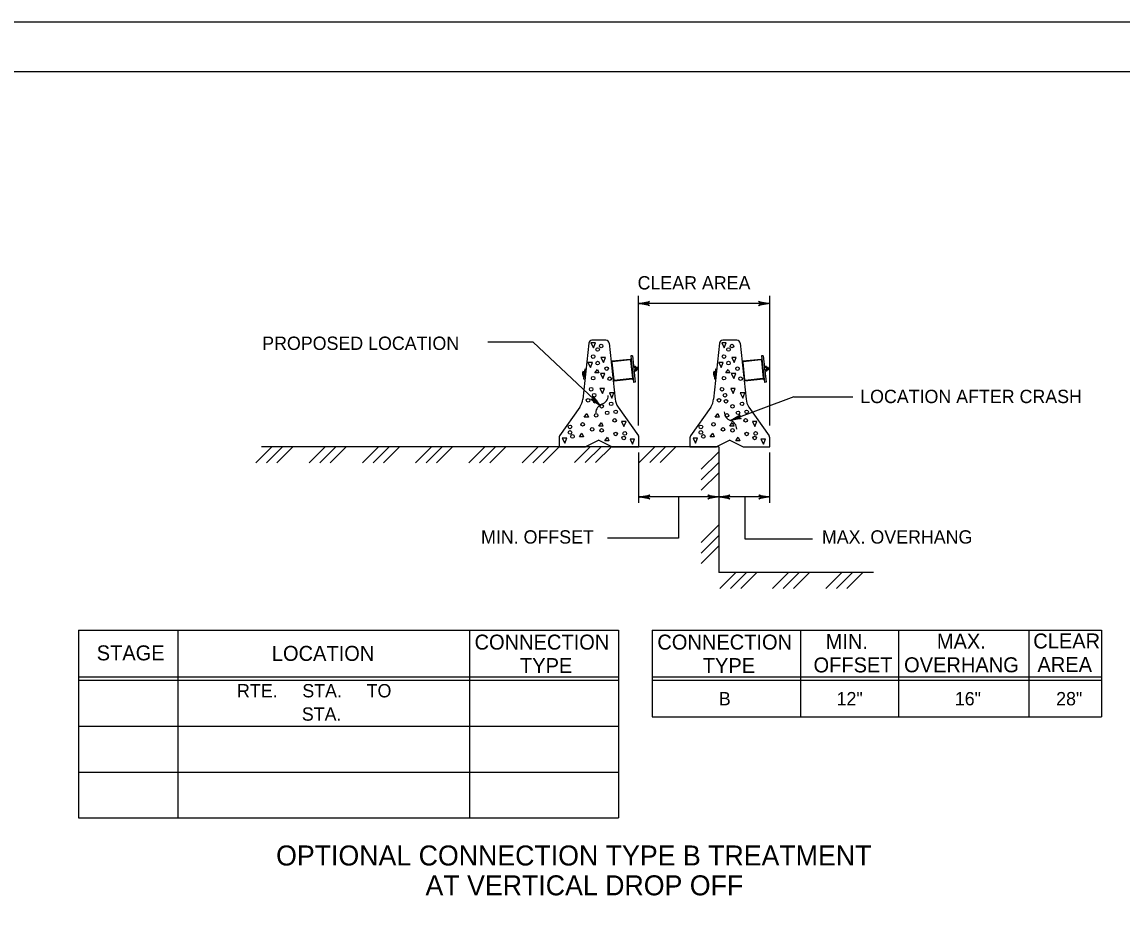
# Model space of a CAD drawing. Extents: x 499909 to 500993, y 502505 to 503165.
# Drawn here: x 500297.3 to 500627.6, y 502894.5 to 503165 of the extents above; entities that cross this region are included whole.
import ezdxf

# ---------------------------------------------------------------- set-up
doc = ezdxf.new("R2010")
doc.units = 0
for name, color, linetype in [('1', 7, 'Continuous'), ('24', 7, 'Continuous'), ('3', 7, 'Continuous'), ('41', 7, 'Continuous'), ('5', 7, 'Continuous')]:
    doc.layers.add(name, color=color, linetype=linetype)

msp = doc.modelspace()

# ---------------------------------------------------------------- linework, layer by layer
at = {"layer": '1'}
for p, q in [((500993, 503165), (499944.83, 503165)), ((500990, 503150), (500000, 503150)), ((500367.51, 503032.66), (500372.22, 503037.37)), ((500506.51, 503037.49), (500369.24, 503037.49)), ((500370.71, 503032.66), (500375.43, 503037.37)), ((500373.82, 503032.66), (500378.53, 503037.37)), ((500383.5, 503032.66), (500388.21, 503037.37)), ((500386.7, 503032.66), (500391.41, 503037.37)), ((500389.8, 503032.66), (500394.52, 503037.37)), ((500399.48, 503032.66), (500404.2, 503037.37)), ((500402.69, 503032.66), (500407.4, 503037.37)), ((500405.79, 503032.66), (500410.5, 503037.37)), ((500415.47, 503032.66), (500420.18, 503037.37)), ((500418.68, 503032.66), (500423.39, 503037.37)), ((500421.78, 503032.66), (500426.49, 503037.37)), ((500431.46, 503032.66), (500436.17, 503037.37)), ((500434.66, 503032.66), (500439.38, 503037.37)), ((500437.77, 503032.66), (500442.48, 503037.37)), ((500447.45, 503032.66), (500452.16, 503037.37)), ((500450.65, 503032.66), (500455.36, 503037.37)), ((500453.76, 503032.66), (500458.47, 503037.37)), ((500463.22, 503032.78), (500467.93, 503037.49)), ((500466.42, 503032.78), (500471.14, 503037.49)), ((500469.53, 503032.78), (500474.24, 503037.49)), ((500482.61, 503032.78), (500487.32, 503037.49)), ((500485.81, 503032.78), (500490.52, 503037.49)), ((500488.91, 503032.78), (500493.63, 503037.49)), ((500501.24, 503030.74), (500506.51, 503036.01)), ((500506.51, 503037.49), (500506.51, 502999.74)), ((500501.24, 503027.53), (500506.51, 503032.8)), ((500501.24, 503024.43), (500506.51, 503029.7)), ((500501.24, 503008.75), (500506.51, 503014.02)), ((500501.24, 503005.55), (500506.51, 503010.82)), ((500501.24, 503002.44), (500506.51, 503007.72)), ((500552.96, 502999.74), (500506.51, 502999.74)), ((500506.83, 502994.97), (500511.55, 502999.69)), ((500510.04, 502994.97), (500514.75, 502999.69)), ((500513.14, 502994.97), (500517.85, 502999.69)), ((500522.62, 502994.97), (500527.33, 502999.69)), ((500525.82, 502994.97), (500530.53, 502999.69)), ((500528.92, 502994.97), (500533.64, 502999.69)), ((500538.68, 502994.97), (500543.39, 502999.69)), ((500541.88, 502994.97), (500546.59, 502999.69)), ((500544.99, 502994.97), (500549.7, 502999.69)), ((500314.25, 502982.41), (500314.25, 502926.08)), ((500314.25, 502982.41), (500344.11, 502982.41)), ((500344.11, 502982.41), (500344.11, 502926.08)), ((500344.11, 502982.41), (500431.62, 502982.41)), ((500431.62, 502982.41), (500431.62, 502926.08)), ((500431.62, 502982.41), (500476.34, 502982.41)), ((500476.34, 502982.41), (500476.34, 502926.08)), ((500486.54, 502982.41), (500621.37, 502982.41)), ((500486.54, 502982.41), (500486.54, 502956.43)), ((500531.04, 502982.41), (500531.04, 502956.43)), ((500560.49, 502982.41), (500560.49, 502956.43)), ((500599.63, 502982.41), (500599.63, 502956.43)), ((500621.37, 502982.41), (500621.37, 502956.43)), ((500314.25, 502968.42), (500476.34, 502968.42)), ((500314.25, 502967.42), (500476.34, 502967.42)), ((500486.54, 502968.42), (500621.37, 502968.42)), ((500486.54, 502967.42), (500621.37, 502967.42)), ((500486.54, 502956.43), (500621.37, 502956.43)), ((500314.25, 502953.64), (500476.34, 502953.64)), ((500314.25, 502939.86), (500476.34, 502939.86)), ((500314.25, 502926.08), (500476.34, 502926.08))]:
    msp.add_line(p, q, dxfattribs=at)
at = {"layer": '24'}
for points in [[(500482.35, 503080.5), (500485.67, 503081.09), (500484.88, 503080.5), (500485.66, 503079.92), (500482.35, 503080.5), (500482.57, 503080.49), (500485.58, 503081.04), (500484.82, 503080.49), (500485.52, 503079.97), (500482.69, 503080.48), (500482.8, 503080.5), (500485.38, 503080.96), (500484.8, 503080.49), (500485.39, 503080.04), (500482.85, 503080.5), (500482.96, 503080.48), (500485.21, 503080.89), (500484.78, 503080.5), (500485.22, 503080.09), (500483.28, 503080.48), (500483.47, 503080.48), (500485.05, 503080.8), (500484.74, 503080.51), (500485.07, 503080.18), (500483.5, 503080.5), (500483.68, 503080.51), (500484.87, 503080.71), (500484.64, 503080.48), (500484.89, 503080.25), (500483.84, 503080.5), (500484.01, 503080.52), (500484.72, 503080.65), (500484.6, 503080.49), (500484.8, 503080.31), (500484.1, 503080.5), (500484.56, 503080.61), (500484.49, 503080.48), (500484.7, 503080.35), (500484.21, 503080.48), (500484.52, 503080.56), (500484.39, 503080.46), (500484.54, 503080.4), (500484.39, 503080.49), (500484.47, 503080.51)], [(500521.78, 503080.5), (500518.45, 503079.91), (500519.25, 503080.5), (500518.47, 503081.08), (500521.78, 503080.5), (500521.55, 503080.5), (500518.54, 503079.95), (500519.31, 503080.51), (500518.6, 503081.03), (500521.44, 503080.51), (500521.33, 503080.5), (500518.75, 503080.04), (500519.33, 503080.51), (500518.73, 503080.96), (500521.27, 503080.5), (500521.16, 503080.51), (500518.91, 503080.11), (500519.35, 503080.5), (500518.9, 503080.9), (500520.84, 503080.52), (500520.66, 503080.51), (500519.08, 503080.19), (500519.38, 503080.49), (500519.05, 503080.82), (500520.62, 503080.5), (500520.44, 503080.49), (500519.26, 503080.28), (500519.49, 503080.52), (500519.24, 503080.74), (500520.28, 503080.5), (500520.11, 503080.48), (500519.4, 503080.35), (500519.52, 503080.51), (500519.32, 503080.68), (500520.03, 503080.5), (500519.56, 503080.39), (500519.63, 503080.51), (500519.43, 503080.64), (500519.91, 503080.52), (500519.61, 503080.44), (500519.73, 503080.54), (500519.59, 503080.6), (500519.73, 503080.51), (500519.66, 503080.49)], [(500470.82, 503050.03), (500468.8, 503052.67), (500468.99, 503051.72), (500468.04, 503051.82), (500470.82, 503050.03), (500470.66, 503050.17), (500468.84, 503052.58), (500469.03, 503051.67), (500468.16, 503051.76), (500470.56, 503050.25), (500470.49, 503050.33), (500468.93, 503052.38), (500469.04, 503051.66), (500468.31, 503051.73), (500470.46, 503050.37), (500470.37, 503050.43), (500469, 503052.22), (500469.06, 503051.65), (500468.47, 503051.65), (500470.13, 503050.64), (500470, 503050.77), (500469.07, 503052.05), (500469.09, 503051.63), (500468.63, 503051.61), (500469.98, 503050.8), (500469.86, 503050.93), (500469.14, 503051.86), (500469.15, 503051.54), (500468.82, 503051.54), (500469.74, 503051.03), (500469.63, 503051.15), (500469.2, 503051.72), (500469.18, 503051.53), (500468.92, 503051.53), (500469.55, 503051.2), (500469.29, 503051.59), (500469.25, 503051.45), (500469.02, 503051.49), (500469.46, 503051.26), (500469.29, 503051.52), (500469.31, 503051.36), (500469.17, 503051.42), (500469.33, 503051.39), (500469.29, 503051.45)], [(500510.01, 503045.39), (500512.88, 503047.08), (500512.34, 503046.26), (500513.26, 503045.99), (500510.01, 503045.39), (500510.21, 503045.46), (500512.8, 503047), (500512.29, 503046.23), (500513.12, 503045.99), (500510.33, 503045.49), (500510.43, 503045.55), (500512.65, 503046.86), (500512.27, 503046.23), (500512.98, 503046.01), (500510.47, 503045.56), (500510.58, 503045.59), (500512.52, 503046.74), (500512.25, 503046.23), (500512.8, 503046.01), (500510.88, 503045.7), (500511.05, 503045.76), (500512.39, 503046.6), (500512.21, 503046.22), (500512.63, 503046.03), (500511.07, 503045.79), (500511.23, 503045.86), (500512.26, 503046.45), (500512.13, 503046.16), (500512.43, 503046.04), (500511.39, 503045.9), (500511.54, 503045.98), (500512.15, 503046.35), (500512.09, 503046.16), (500512.34, 503046.06), (500511.62, 503045.99), (500512.01, 503046.25), (500512, 503046.11), (500512.23, 503046.07), (500511.74, 503046.02), (500511.99, 503046.19), (500511.91, 503046.06), (500512.06, 503046.05), (500511.9, 503046.09), (500511.96, 503046.13)], [(500482.5, 503022.42), (500485.83, 503023.01), (500485.03, 503022.42), (500485.81, 503021.84), (500482.5, 503022.42), (500482.72, 503022.42), (500485.73, 503022.97), (500484.97, 503022.42), (500485.67, 503021.89), (500482.84, 503022.41), (500482.95, 503022.42), (500485.53, 503022.88), (500484.95, 503022.42), (500485.55, 503021.97), (500483, 503022.42), (500483.11, 503022.41), (500485.37, 503022.81), (500484.93, 503022.42), (500485.38, 503022.02), (500483.44, 503022.41), (500483.62, 503022.41), (500485.2, 503022.73), (500484.89, 503022.43), (500485.22, 503022.1), (500483.66, 503022.42), (500483.83, 503022.43), (500485.02, 503022.64), (500484.79, 503022.41), (500485.04, 503022.18), (500484, 503022.42), (500484.16, 503022.44), (500484.88, 503022.58), (500484.76, 503022.42), (500484.95, 503022.24), (500484.25, 503022.42), (500484.72, 503022.53), (500484.65, 503022.41), (500484.85, 503022.28), (500484.37, 503022.41), (500484.67, 503022.48), (500484.54, 503022.38), (500484.69, 503022.32), (500484.55, 503022.42), (500484.62, 503022.43)], [(500506.51, 503022.43), (500503.19, 503021.84), (500503.98, 503022.43), (500503.2, 503023.01), (500506.51, 503022.43), (500506.29, 503022.43), (500503.28, 503021.88), (500504.04, 503022.43), (500503.34, 503022.96), (500506.17, 503022.44), (500506.06, 503022.43), (500503.48, 503021.97), (500504.06, 503022.43), (500503.47, 503022.89), (500506.01, 503022.43), (500505.9, 503022.44), (500503.65, 503022.04), (500504.08, 503022.43), (500503.64, 503022.83), (500505.58, 503022.44), (500505.39, 503022.44), (500503.81, 503022.12), (500504.12, 503022.42), (500503.79, 503022.75), (500505.36, 503022.43), (500505.18, 503022.42), (500503.99, 503022.21), (500504.22, 503022.44), (500503.97, 503022.67), (500505.02, 503022.43), (500504.85, 503022.41), (500504.14, 503022.27), (500504.25, 503022.43), (500504.06, 503022.61), (500504.76, 503022.43), (500504.3, 503022.32), (500504.37, 503022.44), (500504.16, 503022.57), (500504.65, 503022.44), (500504.34, 503022.37), (500504.47, 503022.47), (500504.32, 503022.53), (500504.47, 503022.43), (500504.39, 503022.42)], [(500506.51, 503022.42), (500509.83, 503023.01), (500509.04, 503022.42), (500509.82, 503021.84), (500506.51, 503022.42), (500506.73, 503022.42), (500509.74, 503022.97), (500508.98, 503022.42), (500509.68, 503021.89), (500506.85, 503022.41), (500506.96, 503022.42), (500509.54, 503022.88), (500508.96, 503022.42), (500509.56, 503021.97), (500507.01, 503022.42), (500507.12, 503022.41), (500509.38, 503022.81), (500508.94, 503022.42), (500509.38, 503022.02), (500507.44, 503022.41), (500507.63, 503022.41), (500509.21, 503022.73), (500508.9, 503022.43), (500509.23, 503022.1), (500507.66, 503022.42), (500507.84, 503022.43), (500509.03, 503022.64), (500508.8, 503022.41), (500509.05, 503022.18), (500508, 503022.42), (500508.17, 503022.44), (500508.88, 503022.58), (500508.77, 503022.42), (500508.96, 503022.24), (500508.26, 503022.42), (500508.72, 503022.53), (500508.66, 503022.41), (500508.86, 503022.28), (500508.38, 503022.41), (500508.68, 503022.48), (500508.55, 503022.38), (500508.7, 503022.32), (500508.55, 503022.42), (500508.63, 503022.43)], [(500521.82, 503022.43), (500518.5, 503021.84), (500519.29, 503022.43), (500518.52, 503023.01), (500521.82, 503022.43), (500521.6, 503022.43), (500518.59, 503021.88), (500519.35, 503022.43), (500518.65, 503022.96), (500521.48, 503022.44), (500521.37, 503022.43), (500518.79, 503021.97), (500519.37, 503022.43), (500518.78, 503022.89), (500521.32, 503022.43), (500521.21, 503022.44), (500518.96, 503022.04), (500519.39, 503022.43), (500518.95, 503022.83), (500520.89, 503022.44), (500520.7, 503022.44), (500519.12, 503022.12), (500519.43, 503022.42), (500519.1, 503022.75), (500520.67, 503022.43), (500520.49, 503022.42), (500519.3, 503022.21), (500519.53, 503022.44), (500519.29, 503022.67), (500520.33, 503022.43), (500520.16, 503022.41), (500519.45, 503022.27), (500519.57, 503022.43), (500519.37, 503022.61), (500520.07, 503022.43), (500519.61, 503022.32), (500519.68, 503022.44), (500519.47, 503022.57), (500519.96, 503022.44), (500519.65, 503022.37), (500519.78, 503022.47), (500519.63, 503022.53), (500519.78, 503022.43), (500519.7, 503022.42)]]:
    msp.add_lwpolyline(points, dxfattribs=at)
for centre, start, end in [((500470.53, 503052.9), 288.8004, 359.1656), ((500472.31, 503047.66), 108.8004, 179.1656), ((500510.9, 503048.01), 180.8344, 251.1996), ((500509.12, 503042.77), 0.8344, 71.1996)]:
    msp.add_arc(centre, 2.77, start, end, dxfattribs=at)
at = {"layer": '3'}
for p, q in [((500521.78, 503080.5), (500482.35, 503080.5)), ((500467.44, 503068.59), (500465.67, 503051.77)), ((500472.63, 503069.48), (500468.43, 503069.48)), ((500473.62, 503068.59), (500475.39, 503051.77)), ((500506.73, 503068.59), (500504.96, 503051.77)), ((500511.92, 503069.48), (500507.72, 503069.48)), ((500512.92, 503068.59), (500514.68, 503051.77)), ((500480.55, 503064.82), (500480.06, 503064.76)), ((500480.06, 503064.76), (500480.89, 503056.81)), ((500480.55, 503064.82), (500481.39, 503056.86)), ((500519.85, 503064.82), (500519.35, 503064.76)), ((500519.35, 503064.76), (500520.18, 503056.81)), ((500519.85, 503064.82), (500520.68, 503056.86)), ((500474.22, 503062.9), (500474.79, 503057.43)), ((500474.22, 503062.9), (500474.79, 503057.43)), ((500474.41, 503062.85), (500474.97, 503057.51)), ((500479.91, 503063.74), (500474.44, 503063.17)), ((500479.87, 503063.55), (500474.52, 503062.99)), ((500480.01, 503063.44), (500480.57, 503058.09)), ((500481.46, 503061.64), (500480.95, 503061.59)), ((500481.53, 503061.46), (500481.65, 503060.34)), ((500482.05, 503061.33), (500481.55, 503061.28)), ((500482.05, 503061.33), (500482.13, 503060.58)), ((500513.51, 503062.9), (500514.09, 503057.43)), ((500513.51, 503062.9), (500514.09, 503057.43)), ((500513.71, 503062.85), (500514.27, 503057.51)), ((500519.21, 503063.74), (500513.73, 503063.17)), ((500519.16, 503063.55), (500513.82, 503062.99)), ((500519.3, 503063.44), (500519.86, 503058.09)), ((500520.75, 503061.64), (500520.25, 503061.59)), ((500520.83, 503061.46), (500520.94, 503060.34)), ((500521.34, 503061.33), (500520.85, 503061.28)), ((500521.34, 503061.33), (500521.42, 503060.58)), ((500465.78, 503060.17), (500465.97, 503058.4)), ((500466.13, 503059.68), (500465.84, 503059.65)), ((500466.05, 503058.92), (500465.91, 503058.91)), ((500466.25, 503060.85), (500465.93, 503057.87)), ((500466.04, 503058.92), (500466.42, 503058.88)), ((500466.14, 503059.79), (500466.51, 503059.75)), ((500466.25, 503060.85), (500466.62, 503060.81)), ((500481.49, 503061.27), (500480.99, 503061.22)), ((500481.57, 503060.52), (500481.07, 503060.47)), ((500481.61, 503060.15), (500481.11, 503060.1)), ((500482.13, 503060.58), (500481.63, 503060.53)), ((500481.69, 503061.17), (500481.74, 503060.67)), ((500481.8, 503061.3), (500481.88, 503060.56)), ((500481.94, 503061.19), (500481.99, 503060.69)), ((500505.08, 503060.17), (500505.26, 503058.4)), ((500505.42, 503059.68), (500505.13, 503059.65)), ((500505.34, 503058.92), (500505.21, 503058.91)), ((500505.54, 503060.85), (500505.23, 503057.87)), ((500505.34, 503058.92), (500505.71, 503058.88)), ((500505.43, 503059.79), (500505.8, 503059.75)), ((500505.54, 503060.85), (500505.91, 503060.81)), ((500520.79, 503061.27), (500520.28, 503061.22)), ((500520.87, 503060.52), (500520.36, 503060.47)), ((500520.9, 503060.15), (500520.4, 503060.1)), ((500521.42, 503060.58), (500520.93, 503060.53)), ((500520.98, 503061.17), (500521.04, 503060.67)), ((500521.1, 503061.3), (500521.17, 503060.56)), ((500521.23, 503061.19), (500521.29, 503060.69)), ((500465.93, 503057.87), (500466.31, 503057.83)), ((500480.54, 503057.78), (500475.07, 503057.2)), ((500480.46, 503057.96), (500475.11, 503057.4)), ((500481.39, 503056.86), (500480.89, 503056.81)), ((500505.23, 503057.87), (500505.6, 503057.83)), ((500519.83, 503057.78), (500514.36, 503057.2)), ((500519.75, 503057.96), (500514.4, 503057.4)), ((500520.68, 503056.86), (500520.18, 503056.81)), ((500464.79, 503049.43), (500458.71, 503040.75)), ((500476.26, 503049.43), (500482.35, 503040.75)), ((500504.09, 503049.43), (500498, 503040.75)), ((500515.56, 503049.43), (500521.64, 503040.75)), ((500458.53, 503040.17), (500458.53, 503037.49)), ((500470.53, 503039.49), (500466.53, 503037.49)), ((500470.53, 503039.49), (500474.53, 503037.49)), ((500482.53, 503037.49), (500482.53, 503040.17)), ((500497.82, 503040.17), (500497.82, 503037.49)), ((500509.82, 503039.49), (500505.83, 503037.49)), ((500509.82, 503039.49), (500513.82, 503037.49)), ((500521.82, 503037.49), (500521.82, 503040.17)), ((500458.53, 503037.49), (500466.53, 503037.49)), ((500474.53, 503037.49), (500482.53, 503037.49)), ((500497.82, 503037.49), (500505.83, 503037.49)), ((500513.82, 503037.49), (500521.82, 503037.49)), ((500521.82, 503022.43), (500482.53, 503022.43)), ((500494.38, 503022.43), (500494.38, 503010.09)), ((500514.32, 503022.43), (500514.32, 503009.9)), ((500494.38, 503010.09), (500473.06, 503010.09)), ((500514.32, 503009.9), (500534.62, 503009.9))]:
    msp.add_line(p, q, dxfattribs=at)
for centre, radius, start, end in [((500468.43, 503068.48), 1, 90, 174.0136), ((500472.63, 503068.48), 1, 5.9864, 90), ((500507.72, 503068.48), 1, 90, 174.0136), ((500511.92, 503068.48), 1, 5.9864, 90), ((500474.47, 503062.92), 0.25, 95.9864, 185.9864), ((500474.54, 503062.87), 0.125, 95.9864, 185.9864), ((500479.88, 503063.43), 0.125, 5.9864, 95.9864), ((500479.94, 503063.5), 0.25, 5.9864, 95.9864), ((500481.23, 503061.43), 0.323, 150.4975, 221.4763), ((500481.21, 503061.43), 0.323, 330.497, 41.4758), ((500513.76, 503062.92), 0.25, 95.9864, 185.9864), ((500513.83, 503062.87), 0.125, 95.9864, 185.9864), ((500519.18, 503063.43), 0.125, 5.9864, 95.9864), ((500519.23, 503063.5), 0.25, 5.9864, 95.9864), ((500520.53, 503061.43), 0.323, 150.4975, 221.4763), ((500520.51, 503061.43), 0.323, 330.497, 41.4758), ((500467.2, 503059.42), 1.6, 152.1575, 219.8428), ((500480.44, 503058.08), 0.125, 275.9864, 5.9864), ((500480.51, 503058.03), 0.25, 275.9864, 5.9864), ((500482.17, 503060.96), 1.21, 167.8349, 204.1389), ((500481.35, 503060.31), 0.323, 150.4975, 221.4763), ((500480.39, 503060.78), 1.21, 347.8344, 24.1384), ((500481.33, 503060.31), 0.323, 330.497, 41.4758), ((500506.49, 503059.42), 1.6, 152.1575, 219.8428), ((500519.74, 503058.08), 0.125, 275.9864, 5.9864), ((500519.81, 503058.03), 0.25, 275.9864, 5.9864), ((500521.46, 503060.96), 1.21, 167.8349, 204.1389), ((500520.64, 503060.31), 0.323, 150.4975, 221.4763), ((500519.69, 503060.78), 1.21, 347.8344, 24.1384), ((500520.62, 503060.31), 0.323, 330.497, 41.4758), ((500475.04, 503057.45), 0.25, 185.9864, 275.9864), ((500475.1, 503057.52), 0.125, 185.9864, 275.9864), ((500514.33, 503057.45), 0.25, 185.9864, 275.9864), ((500514.39, 503057.52), 0.125, 185.9864, 275.9864), ((500460.7, 503052.3), 5, 324.969, 354.0136), ((500480.36, 503052.3), 5, 185.9864, 215.0335), ((500499.99, 503052.3), 5, 324.969, 354.0136), ((500519.65, 503052.3), 5, 185.9864, 215.0335), ((500459.53, 503040.17), 1, 144.969, 180), ((500481.53, 503040.17), 1, 0, 35.0335), ((500498.82, 503040.17), 1, 144.969, 180), ((500520.82, 503040.17), 1, 0, 35.0335)]:
    msp.add_arc(centre, radius, start, end, dxfattribs=at)
at = {"layer": '41'}
msp.add_lwpolyline([(499944.83, 502505), (500993, 502505), (500993, 503165), (499944.83, 503165)], close=True, dxfattribs=at)
for centre in [(500466.99, 503059.38), (500506.28, 503059.38)]:
    msp.add_arc(centre, 1.6, 151.6724, 151.7004, dxfattribs=at)
at = {"layer": '5'}
for p, q in [((500482.35, 503043.85), (500482.35, 503082.84)), ((500521.78, 503043.85), (500521.78, 503082.84)), ((500450.73, 503068.86), (500437.14, 503068.86)), ((500450.73, 503068.86), (500470.64, 503050.14)), ((500528.99, 503052.53), (500510.01, 503045.39)), ((500528.99, 503052.53), (500546.77, 503052.53)), ((500482.53, 503020.63), (500482.53, 503035.73)), ((500521.82, 503020.63), (500521.82, 503035.73))]:
    msp.add_line(p, q, dxfattribs=at)
for points in [[(500469.45, 503068.71), (500468.09, 503068.71), (500468.85, 503067.21)], [(500508.74, 503068.71), (500507.39, 503068.71), (500508.14, 503067.21)], [(500468.55, 503062.83), (500467.19, 503062.83), (500467.94, 503061.33)], [(500472.47, 503064.34), (500471.11, 503064.34), (500471.86, 503062.83)], [(500507.84, 503062.83), (500506.48, 503062.83), (500507.24, 503061.33)], [(500511.76, 503064.34), (500510.4, 503064.34), (500511.15, 503062.83)], [(500470.51, 503059.67), (500469.3, 503059.67), (500470.05, 503060.72)], [(500472.31, 503059.52), (500470.96, 503059.52), (500471.71, 503058.01)], [(500509.8, 503059.67), (500508.59, 503059.67), (500509.35, 503060.72)], [(500511.61, 503059.52), (500510.25, 503059.52), (500511, 503058.01)], [(500472.16, 503054.99), (500470.81, 503054.99), (500471.56, 503053.49)], [(500472.16, 503054.99), (500470.81, 503054.99), (500471.56, 503053.49)], [(500511.46, 503054.99), (500510.1, 503054.99), (500510.85, 503053.49)], [(500511.46, 503054.99), (500510.1, 503054.99), (500510.85, 503053.49)], [(500475.03, 503053.64), (500473.67, 503053.64), (500474.43, 503052.13)], [(500514.32, 503053.64), (500512.96, 503053.64), (500513.72, 503052.13)], [(500467.34, 503046.4), (500466.13, 503046.4), (500466.89, 503047.46)], [(500478.65, 503045.04), (500477.29, 503045.04), (500478.04, 503043.54)], [(500506.63, 503046.4), (500505.43, 503046.4), (500506.18, 503047.46)], [(500517.94, 503045.04), (500516.58, 503045.04), (500517.34, 503043.54)], [(500465.83, 503040.52), (500464.63, 503040.52), (500465.38, 503041.58)], [(500471.71, 503043.69), (500470.51, 503043.69), (500471.26, 503044.74)], [(500505.12, 503040.52), (500503.92, 503040.52), (500504.67, 503041.58)], [(500511, 503043.69), (500509.8, 503043.69), (500510.55, 503044.74)], [(500460.86, 503040.07), (500459.5, 503040.07), (500460.25, 503038.56)], [(500473.52, 503039.32), (500472.31, 503039.32), (500473.07, 503040.37)], [(500481.21, 503039.77), (500479.85, 503039.77), (500480.61, 503038.26)], [(500500.15, 503040.07), (500498.79, 503040.07), (500499.55, 503038.56)], [(500512.81, 503039.32), (500511.61, 503039.32), (500512.36, 503040.37)], [(500520.5, 503039.77), (500519.14, 503039.77), (500519.9, 503038.26)]]:
    msp.add_lwpolyline(points, close=True, dxfattribs=at)
for centre in [(500471.18, 503067.73), (500510.48, 503067.73), (500468.77, 503064.57), (500470.13, 503066.68), (500508.06, 503064.57), (500509.42, 503066.68), (500470.13, 503062.61), (500472.84, 503060.95), (500509.42, 503062.61), (500512.13, 503060.95), (500468.77, 503058.08), (500468.77, 503058.08), (500473.75, 503057.93), (500473.75, 503057.93), (500508.06, 503058.08), (500508.06, 503058.08), (500513.04, 503057.93), (500513.04, 503057.93), (500468.17, 503054.77), (500468.17, 503054.77), (500507.46, 503054.77), (500507.46, 503054.77), (500467.26, 503051.45), (500469.07, 503052.96), (500469.07, 503052.96), (500469.37, 503051.15), (500506.56, 503051.45), (500508.37, 503052.96), (500508.37, 503052.96), (500508.67, 503051.15), (500471.33, 503049.64), (500472.99, 503047.68), (500474.2, 503050.4), (500475.56, 503047.98), (500510.63, 503049.64), (500512.29, 503047.68), (500513.49, 503050.4), (500514.85, 503047.98), (500469.68, 503046.93), (500475.25, 503045.42), (500508.97, 503046.93), (500514.55, 503045.42), (500461.84, 503043.46), (500461.84, 503041.8), (500465.61, 503044.22), (500468.47, 503042.71), (500471.33, 503042.41), (500475.56, 503041.35), (500478.27, 503041.5), (500501.13, 503043.46), (500501.13, 503041.8), (500504.9, 503044.22), (500507.76, 503042.71), (500510.63, 503042.41), (500514.85, 503041.35), (500517.56, 503041.5), (500462.59, 503040.6), (500477.97, 503040.15), (500501.88, 503040.6), (500517.26, 503040.15)]:
    msp.add_circle(centre, 0.533, dxfattribs=at)

# ---------------------------------------------------------------- texts
at = {"layer": '1'}
for s, height, p in [('CLEAR AREA', 4, (500482.12, 503084.71)), ('PROPOSED LOCATION', 4, (500369.4, 503066.57)), ('MIN. OFFSET', 4, (500435.11, 503008.43)), ('MAX. OVERHANG', 4, (500537.47, 503008.43)), ('CONNECTION', 4.5, (500433.17, 502976.61)), ('CONNECTION', 4.5, (500488.05, 502976.61)), ('MIN.', 4.5, (500538.59, 502976.81)), ('MAX.', 4.5, (500571.98, 502976.86)), ('CLEAR', 4.5, (500600.92, 502976.95)), ('TYPE', 4.5, (500446.81, 502969.55)), ('TYPE', 4.5, (500501.68, 502969.55)), ('OFFSET', 4.5, (500534.95, 502969.76)), ('OVERHANG', 4.5, (500562.14, 502969.8)), ('AREA', 4.5, (500602.19, 502969.89))]:
    msp.add_text(s, height=height, dxfattribs=at).set_placement(p)
msp.add_text('LOCATION AFTER CRASH', height=4, rotation=360, dxfattribs=at).set_placement((500548.96, 503050.6))
at = {"layer": '3'}
for s, p in [('STAGE', (500319.72, 502973.38)), ('LOCATION', (500372.3, 502973.23))]:
    msp.add_text(s, height=4.5, dxfattribs=at).set_placement(p)
at = {"layer": '5'}
for s, height, p in [('RTE.     STA.     TO', 4, (500361.84, 502962.27)), ('B', 4, (500506.52, 502959.88)), ('12"', 4, (500541.87, 502959.88)), ('16"', 4, (500577.37, 502959.88)), ('28"', 4, (500607.8, 502959.88)), ('STA.', 4, (500381.31, 502955.27)), ('OPTIONAL CONNECTION TYPE B TREATMENT', 6, (500373.58, 502911.81)), ('AT VERTICAL DROP OFF', 6, (500418.44, 502902.85))]:
    msp.add_text(s, height=height, dxfattribs=at).set_placement(p)

doc.saveas('drawing.dxf')
